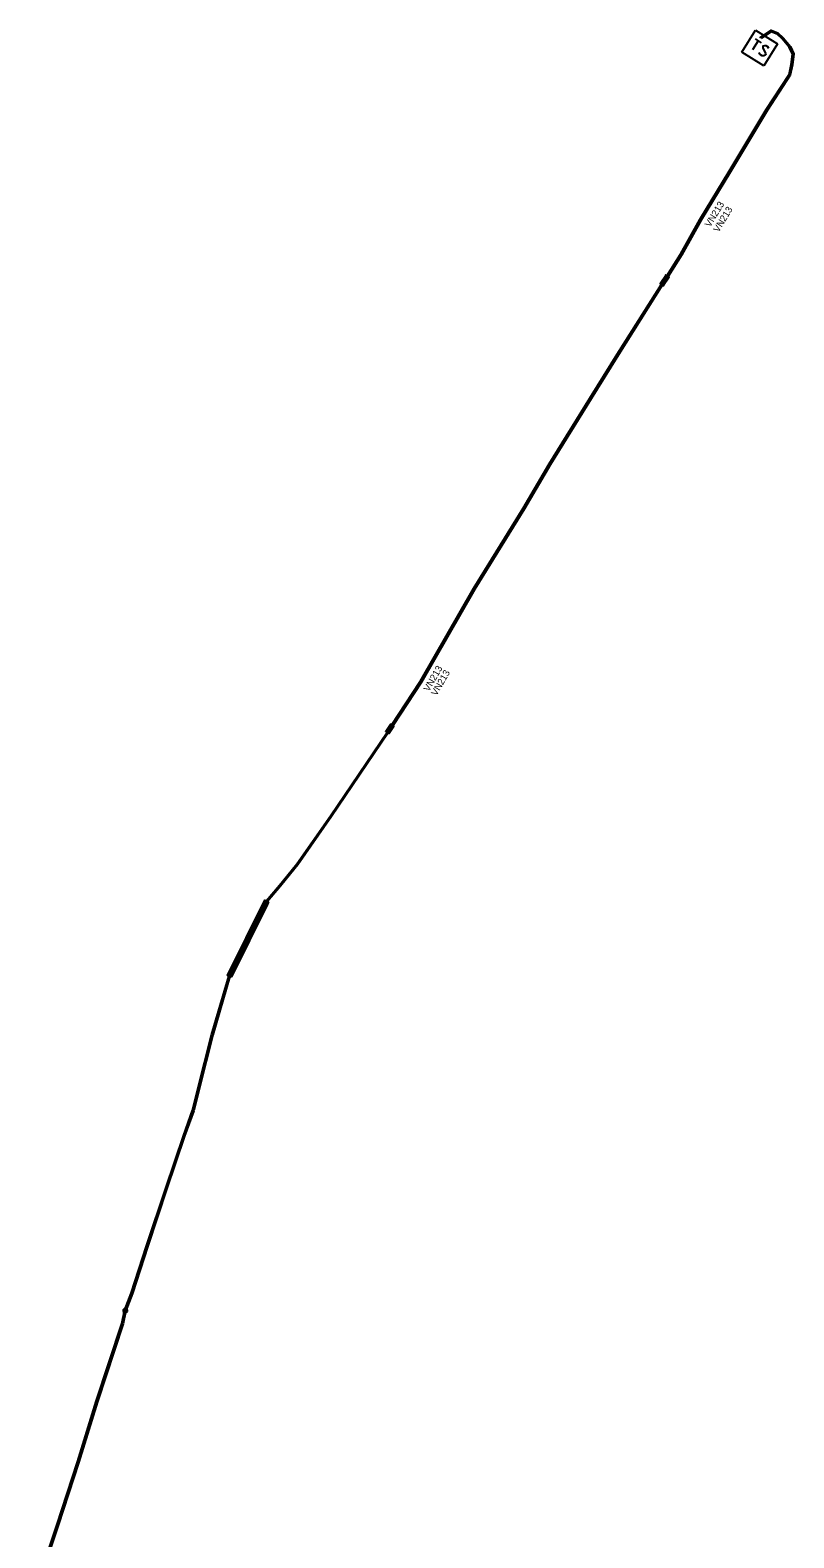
# Model space of a CAD drawing. Extents: x -643811 to -636362, y -1117362 to -1108614.
# Drawn here: x -642152.9 to -642040.9, y -1113668.7 to -1113447.6 of the extents above; entities that cross this region are included whole.
import ezdxf

# ---------------------------------------------------------------- set-up
doc = ezdxf.new("R2010")
doc.units = 0
for name, color, linetype in [('19', 7, 'Continuous'), ('20', 7, 'Continuous'), ('25', 7, 'Continuous'), ('5', 7, 'Continuous'), ('7', 7, 'Continuous')]:
    doc.layers.add(name, color=color, linetype=linetype)

# ---------------------------------------------------------------- blocks, each defined once
blk = doc.blocks.new('VN870')
at = {"layer": '19'}
for points in [[(0, -0.25), (0.5, 0), (0, 0.25), (-0.5, 0), (0, -0.25)], [(0.37, 0), (0, 0.19), (-0.36, 0), (0, -0.19), (0.37, 0)], [(0.24, 0), (0, 0.12), (-0.25, 0), (0, -0.12), (0.24, 0)], [(0.12, 0), (0, 0.06), (-0.13, 0), (0, -0.06), (0.12, 0)]]:
    blk.add_lwpolyline(points, dxfattribs=at)
blk = doc.blocks.new('VN640')
at = {"layer": '25'}
for points in [[(-1.89, 1.89), (1.89, 1.89)], [(-1.89, -1.89), (-1.89, 1.89)], [(-1.26, 0.79), (-0.22, 0.79)], [(-0.73, 0.79), (-0.73, -0.79)], [(1.2, 0.66), (0.94, 0.79), (0.66, 0.79), (0.41, 0.66), (0.28, 0.47), (0.28, 0.41), (0.41, 0.22), (1.13, -0.16), (1.26, -0.32), (1.26, -0.47), (1.13, -0.66), (0.91, -0.79), (0.63, -0.79), (0.5, -0.73), (0.28, -0.6)], [(1.89, 1.89), (1.89, -1.89)], [(1.89, -1.89), (-1.89, -1.89)]]:
    blk.add_lwpolyline(points, dxfattribs=at)

msp = doc.modelspace()

# ---------------------------------------------------------------- linework, layer by layer
at = {"layer": '20'}
for points in [[(-642059.71, -1113483.52), (-642059.7, -1113483.5), (-642059.62, -1113483.56), (-642059.2, -1113483.84), (-642060.02, -1113485.07), (-642060.02, -1113485.08), (-642060.38, -1113484.84), (-642060.52, -1113484.74)], [(-642100.75, -1113550.43), (-642100.07, -1113549.4), (-642099.94, -1113549.49), (-642099.83, -1113549.57), (-642099.57, -1113549.74), (-642100.25, -1113550.77), (-642100.67, -1113550.49), (-642100.73, -1113550.45)], [(-642123.44, -1113586.51), (-642123.44, -1113586.51), (-642123.98, -1113586.25), (-642118.48, -1113575.22), (-642118.31, -1113575.3), (-642117.94, -1113575.48), (-642117.95, -1113575.49), (-642118.1, -1113575.8), (-642123.41, -1113586.44), (-642123.42, -1113586.47)]]:
    msp.add_lwpolyline(points, close=True, dxfattribs=at)
at = {"layer": '5'}
for points in [[(-642045.91, -1113448.72), (-642044.25, -1113447.6), (-642043.25, -1113448), (-642042.48, -1113448.72), (-642041.42, -1113450.01), (-642040.92, -1113451.08), (-642041.1, -1113452.67), (-642041.44, -1113454.18), (-642044.8, -1113459.32), (-642050.2, -1113468.38), (-642054.51, -1113475.46), (-642057.35, -1113480.54), (-642059.37, -1113483.72), (-642060.19, -1113484.96), (-642066.65, -1113495.2), (-642070.66, -1113501.67), (-642076.6, -1113511.32), (-642080.43, -1113517.8), (-642087.7, -1113529.58), (-642095.53, -1113543.22), (-642099.74, -1113549.62), (-642100.42, -1113550.66), (-642108.7, -1113562.95), (-642113.67, -1113570), (-642116.19, -1113573.14), (-642118.13, -1113575.41), (-642123.62, -1113586.42), (-642126.11, -1113595), (-642128.11, -1113602.92), (-642128.89, -1113606.08), (-642130.26, -1113609.83), (-642132.86, -1113617.49), (-642135.64, -1113625.97), (-642137.9, -1113632.91), (-642138.86, -1113635.43), (-642139.29, -1113637.36), (-642143.02, -1113648.77), (-642145.78, -1113657.64), (-642148.8, -1113666.92), (-642152.73, -1113678.61)], [(-642152.91, -1113678.55), (-642148.98, -1113666.86), (-642145.98, -1113657.58), (-642143.22, -1113648.71), (-642139.49, -1113637.3), (-642139.06, -1113635.37), (-642138.08, -1113632.85), (-642135.83, -1113625.91), (-642133.04, -1113617.43), (-642130.44, -1113609.77), (-642129.09, -1113606.02), (-642128.31, -1113602.88), (-642126.31, -1113594.94), (-642123.8, -1113586.34), (-642118.29, -1113575.29), (-642116.35, -1113573.02), (-642113.83, -1113569.88), (-642108.86, -1113562.83), (-642100.58, -1113550.54), (-642099.9, -1113549.52), (-642095.71, -1113543.12), (-642087.88, -1113529.48), (-642080.61, -1113517.7), (-642076.78, -1113511.22), (-642070.83, -1113501.57), (-642066.81, -1113495.1), (-642060.35, -1113484.86), (-642059.53, -1113483.62), (-642057.53, -1113480.44), (-642054.69, -1113475.36), (-642050.38, -1113468.28), (-642044.96, -1113459.22), (-642041.62, -1113454.1), (-642041.3, -1113452.63), (-642041.12, -1113451.12), (-642041.6, -1113450.11), (-642042.62, -1113448.86), (-642043.35, -1113448.18), (-642044.23, -1113447.82), (-642045.73, -1113448.84)]]:
    msp.add_lwpolyline(points, dxfattribs=at)

# ---------------------------------------------------------------- block references
at = {"layer": '19'}
for p, rotation in [((-642139.06, -1113635.37), 70), ((-642138.86, -1113635.43), 69)]:
    msp.add_blockref('VN870', p, dxfattribs=dict(at, rotation=rotation))
at = {"layer": '25', "rotation": -32.00000000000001}
msp.add_blockref('VN640', (-642045.93, -1113450.22), dxfattribs=at)

# ---------------------------------------------------------------- texts
at = {"layer": '7'}
for rotation, p in [(58.6687, (-642053.19, -1113476.58)), (58.6687, (-642051.96, -1113477.33)), (60.1422, (-642094.43, -1113544.69)), (60.1422, (-642093.32, -1113545.32))]:
    msp.add_text('VN213', height=0.994, rotation=rotation, dxfattribs=at).set_placement(p)

doc.saveas('drawing.dxf')
